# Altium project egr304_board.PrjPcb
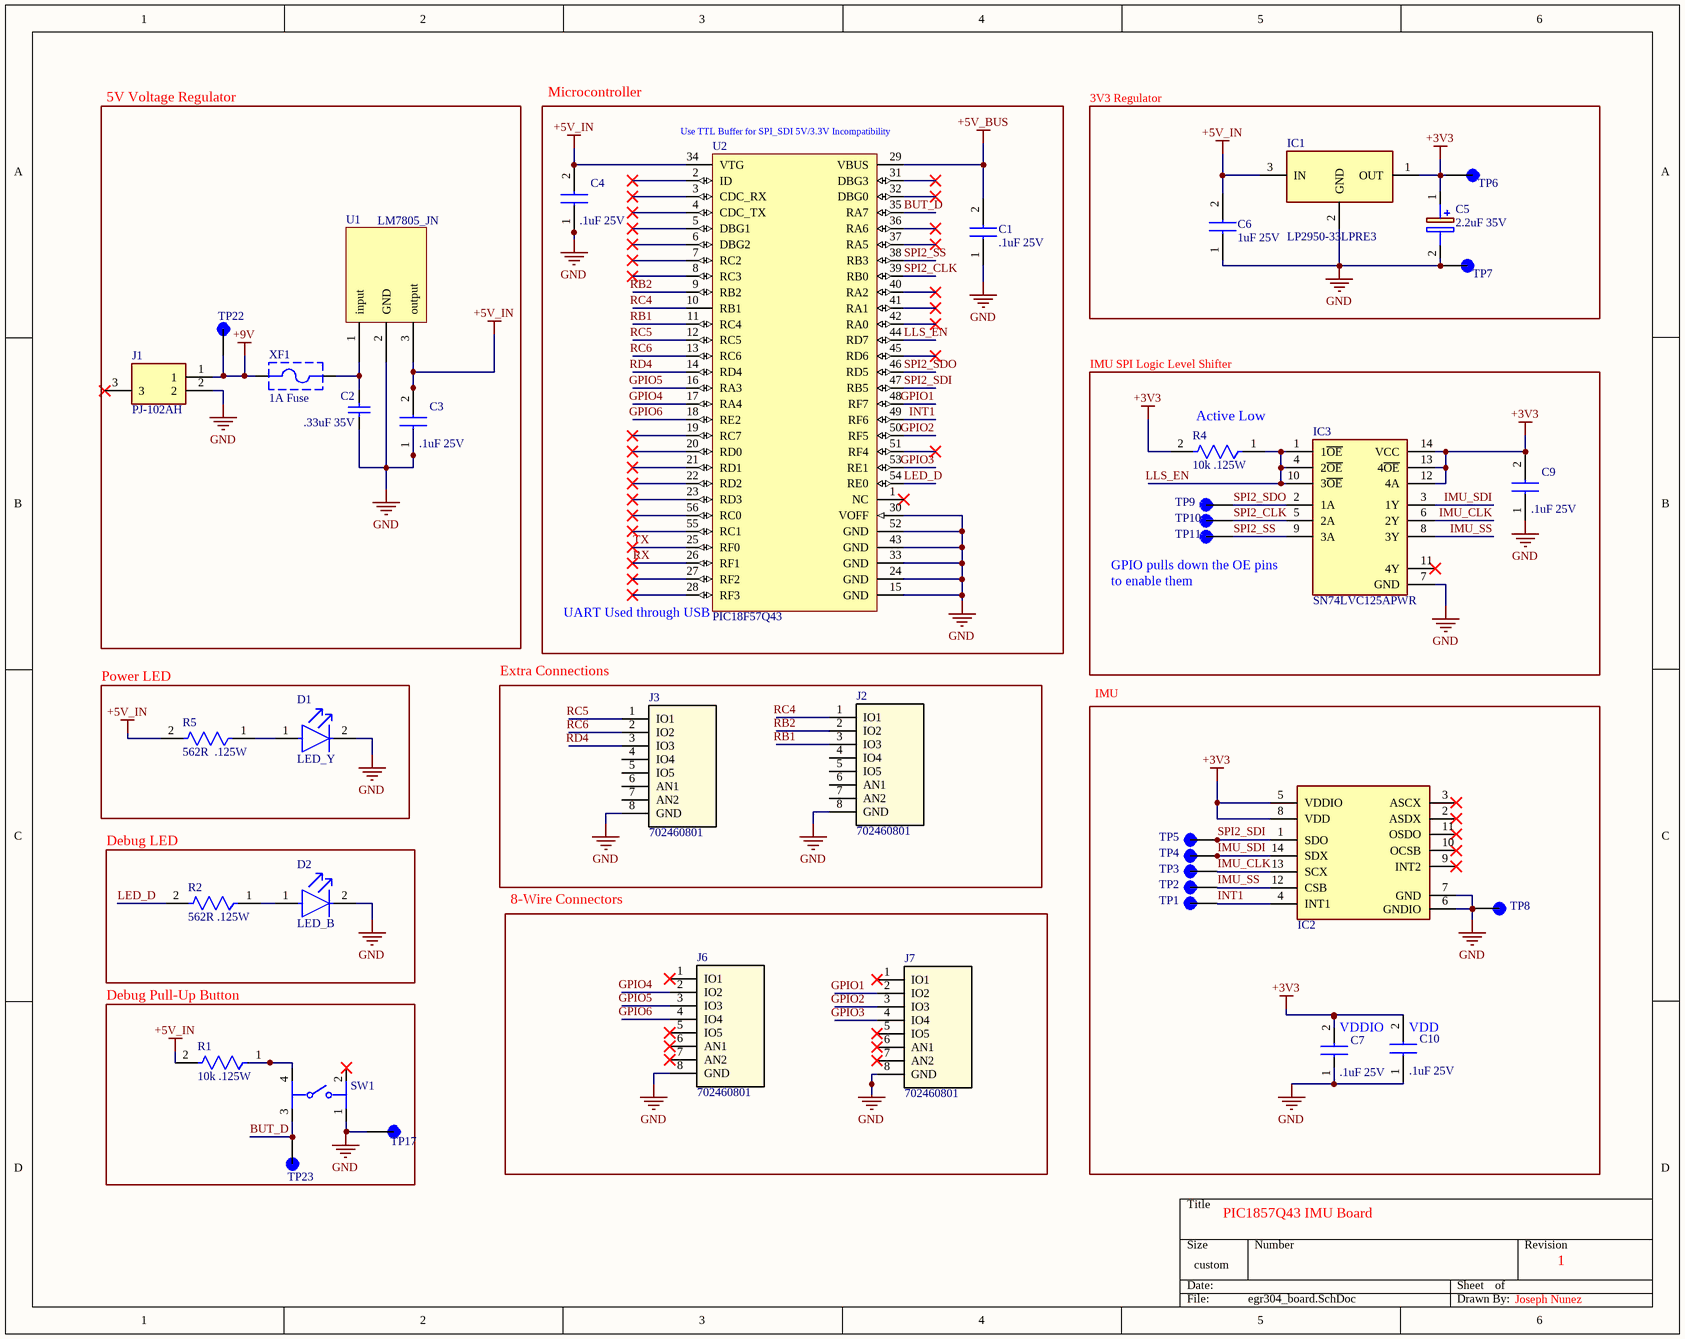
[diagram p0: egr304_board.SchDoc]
1 sheet, 41 parts. Net scope: global (net labels, ports and power ports of the same name join across sheets).
Board file: PCB1.PcbDoc

## Sheet egr304_board.SchDoc
size 314 x 250 mm; SheetNumber: 1; SheetTotal: 1

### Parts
C1  .1uF 25V  [C2012_Commercial]
C2  .33uF 35V  [CAPC2113X120X50LL20T30]
C3  .1uF 25V  [C2012_Commercial]
C4  .1uF 25V  [C2012_Commercial]
C5  2.2uF 35V  [CAPPM3216X180N]
C6  1uF 25V  [C2012_Commercial]
C7  .1uF 25V  [C2012_Commercial]
C9  .1uF 25V  [C2012_Commercial]
C10  .1uF 25V  [C2012_Commercial]
D1  LED_Y  [FP-SM0805YCL-MFG]
D2  LED_B  [FP-SM0805UBWC-MFG]
IC1  LP2950-33LPRE3  [TL431CLPM]
IC2  BMI270  [BMI270]  (value not drawn)
IC3  SN74LVC125APWR  [SN74LVC125APWR]
J1  PJ-102AH  [PJ102AH]
J2  702460801  [CONN_7024608xx_MOL]
J3  702460801  [CONN_7024608xx_MOL]
J6  702460801  [CONN_7024608xx_MOL]
J7  702460801  [CONN_7024608xx_MOL]
R1  10k .125W  [FP-CRGCQ0805-IPC_C]
R2  562R .125W  [FP-RT0805-MFG]
R4  10k .125W  [FP-CRGCQ0805-IPC_C]
R5  562R  .125W  [FP-RT0805-MFG]
SW1  Button  [FP-1301_9320-MFG]  (value not drawn)
TP1  5001  [KEYSTONE_5001]  (value not drawn)
TP2  5001  [KEYSTONE_5001]  (value not drawn)
TP3  5001  [KEYSTONE_5001]  (value not drawn)
TP4  5001  [KEYSTONE_5001]  (value not drawn)
TP5  5001  [KEYSTONE_5001]  (value not drawn)
TP6  5001  [KEYSTONE_5001]  (value not drawn)
TP7  5001  [KEYSTONE_5001]  (value not drawn)
TP8  5001  [KEYSTONE_5001]  (value not drawn)
TP9  5001  [KEYSTONE_5001]  (value not drawn)
TP10  5001  [KEYSTONE_5001]  (value not drawn)
TP11  5001  [KEYSTONE_5001]  (value not drawn)
TP17  5001  [KEYSTONE_5001]  (value not drawn)
TP22  5001  [KEYSTONE_5001]  (value not drawn)
TP23  5001  [KEYSTONE_5001]  (value not drawn)
U1  LM7805_JN  [LM7805_JN]
U2  PIC18F57Q43  [PIC1857Q43_JN]
XF1  1A Fuse  [696101000002]

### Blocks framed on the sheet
5V Voltage Regulator: C2 C3 J1 TP22 U1 XF1
Microcontroller: C1 C4 U2
3V3 Regulator: C5 C6 IC1 TP6 TP7
Active Low: C9 IC3 R4 TP9-TP11
Power LED: D1 R5
Extra Connections: J2 J3
Debug LED: D2 R2
8-Wire Connectors: J6 J7
Debug Pull-Up Button: R1 SW1 TP17 TP23

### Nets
+3V3: C5.1(+) C7.2 C9.2 C10.2 IC1.1(OUT) IC2.5(VDDIO) IC2.8(VDD) IC3.12(4A) IC3.13(4~{OE}) IC3.14(VCC) R4.2 TP6.TP
+5V_BUS: C1.2 U2.29(VBUS)
+5V_IN: C3.2 C4.2 C6.2 IC1.3(IN) R1.2 R5.2 U1.3(output) U2.34(VTG)
+9V: J1.1 TP22.TP XF1.1
GND: C1.1 C2.1 C3.1 C4.1 C5.2(-) C6.1 C7.1 C9.1 C10.1 D1.2(C) D2.2(C) IC1.2(GND) IC2.6(GNDIO) IC2.7(GND) IC3.7(GND) J1.2 J2.8(GND) J3.8(GND) J6.8(GND) J7.8(GND) SW1.1 TP7.TP TP8.TP TP17.TP U1.2(GND) U2.15(GND) U2.24(GND) U2.30(VOFF) U2.33(GND) U2.43(GND) U2.52(GND)
BUT_D: SW1.3 TP23.TP U2.35(RA7)
GPIO1: J7.2(IO2) U2.48(RF7)
GPIO2: J7.3(IO3) U2.50(RF5)
GPIO3: J7.4(IO4) U2.53(RE1)
GPIO4: J6.2(IO2) U2.17(RA4)
GPIO5: J6.3(IO3) U2.16(RA3)
GPIO6: J6.4(IO4) U2.18(RE2)
IMU_CLK: IC2.13(SCX) IC3.6(2Y) TP3.TP
IMU_SDI: IC2.14(SDX) IC3.3(1Y) TP4.TP
IMU_SS: IC2.12(CSB) IC3.8(3Y) TP2.TP
INT1: IC2.4(INT1) TP1.TP U2.49(RF6)
LED_D: R2.2 U2.54(RE0)
LLS_EN: IC3.1(1~{OE}) IC3.4(2~{OE}) IC3.10(3~{OE}) R4.1 U2.44(RD7)
RB1: J2.3(IO3) U2.11(RC4)
RB2: J2.2(IO2) U2.9(RB2)
RC4: J2.1(IO1) U2.10(RB1)
RC5: J3.1(IO1) U2.12(RC5)
RC6: J3.2(IO2) U2.13(RC6)
RD4: J3.3(IO3) U2.14(RD4)
RX: U2.26(RF1)
SPI2_CLK: IC3.5(2A) TP10.TP U2.39(RB0)
SPI2_SDI: IC2.1(SDO) TP5.TP U2.47(RB5)
SPI2_SDO: IC3.2(1A) TP9.TP U2.46(RD5)
SPI2_SS: IC3.9(3A) TP11.TP U2.38(RB3)
TX: U2.25(RF0)
NetC2_2: C2.2 U1.1(input) XF1.2
NetD1_1: D1.1(A) R5.1
NetD2_1: D2.1(A) R2.1
NetR1_1: R1.1 SW1.4

Not connected (* = marked no-connect by the designer): IC2 2(ASDX)* 3(ASCX)* 9(INT2)* 10(OCSB)* 11(OSDO)*; IC3 11(4Y)*; J1 3*; J2 4(IO4) 5(IO5) 6(AN1) 7(AN2); J3 4(IO4) 5(IO5) 6(AN1) 7(AN2); J6 1(IO1)* 5(IO5)* 6(AN1)* 7(AN2)*; J7 1(IO1)* 5(IO5)* 6(AN1)* 7(AN2)*; SW1 2*; U2 1(NC)* 2(ID)* 3(CDC_RX)* 4(CDC_TX)* 5(DBG1)* 6(DBG2)* 7(RC2)* 8(RC3)* 19(RC7)* 20(RD0)* 21(RD1)* 22(RD2)* 23(RD3)* 27(RF2)* 28(RF3)* 31(DBG3)* 32(DBG0)* 36(RA6)* 37(RA5)* 40(RA2)* 41(RA1)* 42(RA0)* 45(RD6)* 51(RF4)* 55(RC1)* 56(RC0)*

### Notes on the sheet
- (near U2) Use TTL Buffer for SPI_SDI 5V/3.3V Incompatibility
- IMU SPI Logic Level Shifter
- (near U2) UART Used through USB
- GPIO pulls down the OE pins
- to enable them
- IMU
- (near C7) VDDIO
- (near C10) VDD
- PIC1857Q43 IMU Board
- 1
- Joseph Nunez

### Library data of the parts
C1 C3 C4 C7 C9 C10 = C2012X7R1V105K085AB: Capacitor / C0805C104J3RACTU / 0805; Manufacturer_Name: TDK
C2 = CMP-2007-04070-1: TAJR334K035RNJ; Manufacturer: AVX Interconnect / Elco
C5 = TPSA225K035R1500: Capacitor Polarised / 1.5ohm ESR for Output Requirement / Tantalum / 1206; Manufacturer_Name: Kyocera AVX
C6 = C2012X7R1V105K085AB: Capacitor / C0805C105K3RACTU / 0805; Manufacturer_Name: TDK
D1 = CMP-35283-000007-1: LED YELLOW CLEAR 0805 SMD / SM0805YCL; Luminous Intensity: 11.5mcd; Test Current: 2mA; Viewing Angle: 130°; Dominant Wavelength: 592nm; Forward Voltage: 1.9V; Lens Color: Colorless
D2 = CMP-35283-000004-1: LED BLUE CLEAR 0805 SMD / SM0805UBWC; Dominant Wavelength: 470nm; Forward Voltage: 3.3V; Forward Current: 20mA; Lens Color: Colorless; Lens Style: Rectangular; Luminous Intensity: 115mcd; Viewing Angle: 130°; Power Rating: 100mW
IC1 = LP2950-33LPRE3: Integrated Circuit; Manufacturer_Name: Texas Instruments
IC2 = BMI270: IMU
IC3 = SN74LVC125APWR: Integrated Circuit; Manufacturer_Name: Texas Instruments
J1 = PJ-102AH: Connector; Manufacturer_Name: Same Sky
J2 J3 J6 J7 = 702460801: 2.54mm Pitch C-Grid Header, Low Profile, Dual Row, Vertical, Shrouded, 8  Circuits, 0.38Âµm Gold (Au) Selective Plating; Manufacturer_Name: Molex Connector Corporation
R1 R4 = CMP-03211-002989-1: CRGCQ0805J10K; Manufacturer: TE Connectivity; Voltage Rating: 150V; Temperature Coefficient: ±100ppm/°C; Resistance: 10KΩ; Value: 10KΩ; Power Rating: 0.125W; Tolerance: 0.05; Automotive Grade: Grade 914
R2 R5 = CMP-03412-035770-1: RES SMD 562 OHM 1% 1/8W 0805 / RC0805FR-07562RL; Manufacturer: Yageo; Manufacturer Part Number: RT0805FRD07562RL; Tolerance: 0.0001; Temperature Coefficient: 25 ppm/°C; Resistance: 562Ω; Power Rating: 0.125W; Voltage Rating: 150V; Value: 562Ω
SW1 = CMP-26321-000001-1: SWITCH TACTILE SPST-NO 0.05A 12V / 1301.9320; Manufacturer: Schurter; Electromechanical Life: 100000Cycles; Contact Current Rating: 50mA; Contact Resistance: 100mΩ; Operating Force: 1.6N
TP1-TP11 TP17 TP22 TP23 = CMP-003-000000-1: MF: Keystone Electronics
U1 = LM7805_JN_1
U2 = PIC18F57Q43_JN
XF1 = CMP-1502-00233-4: WR-FSH Fuse Holder Blocks Fuse Holder Blocks Clip Cover for PCB / 696101000002; Fuse Current: 10A; Voltage Rating (AC): 250V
